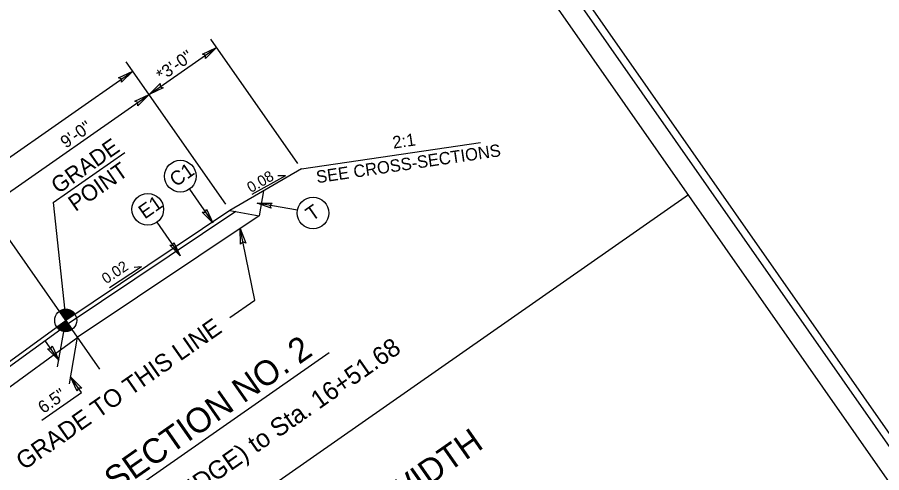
# Model space of a CAD drawing. Extents: x 1033697 to 1037131, y 657437 to 660507.
# Drawn here: x 1036343 to 1036868, y 659641 to 659917 of the extents above; entities that cross this region are included whole.
import ezdxf

# ---------------------------------------------------------------- set-up
doc = ezdxf.new("R2010")
doc.units = 0
for name, color, linetype in [('Default', 7, 'Continuous'), ('Prop Pavement Schedule Description CELL', 7, 'Continuous'), ('Sheet Plot Border Inside CELL', 7, 'Continuous'), ('Sheet Plot Border Outside CELL', 7, 'Continuous'), ('Sheet Typical CELL', 7, 'Continuous'), ('Typical Arrow Superelevation CELL', 7, 'Continuous'), ('Typical Grade Point Symbol CELL', 7, 'Continuous'), ('Typical ID Circle CELL', 7, 'Continuous'), ('Typical Pavement Slope CELL', 7, 'Continuous'), ('Typical Pavement Slope Information CELL', 7, 'Continuous'), ('Typical Shoulder Slope CELL', 7, 'Continuous'), ('Typical Shoulder Slope Information CELL', 7, 'Continuous'), ('Typical Slope Point Local CELL', 7, 'Continuous'), ('Typical Terminator CELL', 7, 'Continuous'), ('Typical Text General CELL', 7, 'Continuous'), ('Typical Text Grade Point CELL', 7, 'Continuous'), ('Typical Text ID Circle CELL', 7, 'Continuous'), ('Typical Text Label CELL', 7, 'Continuous')]:
    doc.layers.add(name, color=color, linetype=linetype)

msp = doc.modelspace()

# ---------------------------------------------------------------- linework, layer by layer
at = {"layer": 'Default'}
for p, q in [((1036513.56, 659828.65), (1036460.77, 659904.21)), ((1036423.33, 659870.49), (1036464.32, 659899.12)), ((1036469.85, 659803.91), (1036409.4, 659890.43)), ((1036216.64, 659747.29), (1036413.38, 659884.73)), ((1036324.96, 659801.76), (1036423.33, 659870.49)), ((1035521.13, 658950.73), (1036750.78, 659809.79)), ((1036393.48, 659703.69), (1036321.41, 659806.85)), ((1036365.07, 659804.89), (1036372.74, 659733.38)), ((1036487.56, 659745.74), (1036478.56, 659789.16)), ((1036472.38, 659735.14), (1036487.56, 659745.74)), ((1036367.74, 659705.17), (1036372.74, 659733.38)), ((1036374.9, 659694.93), (1036379.9, 659723.13)), ((1036368.46, 659709.26), (1036360.5, 659720.65)), ((1036382.24, 659689.54), (1036375.62, 659699.01)), ((1036358.18, 659672.74), (1036382.24, 659689.54))]:
    msp.add_line(p, q, dxfattribs=at)
at = {"layer": 'Sheet Plot Border Inside CELL'}
msp.add_lwpolyline([(1036420.5, 660304.13), (1035054.57, 659349.42), (1035659.01, 658484.62), (1037024.95, 659439.32)], close=True, dxfattribs=at)
at = {"layer": 'Sheet Plot Border Outside CELL'}
msp.add_lwpolyline([(1036411.33, 660325.1), (1035031.05, 659360.38), (1035661.22, 658458.77), (1037041.5, 659423.5)], close=True, dxfattribs=at)
at = {"layer": 'Sheet Typical CELL'}
msp.add_lwpolyline([(1036411.72, 660294.87), (1035182.26, 659435.56), (1035783.78, 658574.94), (1037013.24, 659434.25)], close=True, dxfattribs=at)
at = {"layer": 'Typical Arrow Superelevation CELL'}
for p, q in [((1036506.08, 659821.19), (1036485.7, 659809.88)), ((1036506.08, 659821.19), (1036501.5, 659821.27)), ((1036418.82, 659765.8), (1036399.19, 659753.23)), ((1036418.82, 659765.8), (1036414.25, 659765.59))]:
    msp.add_line(p, q, dxfattribs=at)
at = {"layer": 'Typical Grade Point Symbol CELL'}
for p, q in [((1036372.74, 659733.38), (1036368.89, 659738.88)), ((1036367.24, 659729.53), (1036372.74, 659733.38)), ((1036378.24, 659737.22), (1036372.74, 659733.38)), ((1036376.57, 659727.86), (1036372.74, 659733.38)), ((1036372.74, 659733.38), (1036376.57, 659727.86))]:
    msp.add_line(p, q, dxfattribs=at)
for points in [[(1036368.94, 659738.91), (1036368.94, 659738.91), (1036372.79, 659733.41)], [(1036369.05, 659738.99), (1036372.9, 659733.49)], [(1036369.17, 659739.06), (1036373.01, 659733.56)], [(1036369.28, 659739.13), (1036373.12, 659733.64)], [(1036369.4, 659739.2), (1036373.23, 659733.72)], [(1036369.52, 659739.26), (1036373.34, 659733.79)], [(1036369.64, 659739.33), (1036373.45, 659733.87)], [(1036369.76, 659739.39), (1036373.56, 659733.95)], [(1036369.88, 659739.46), (1036373.67, 659734.03)], [(1036370, 659739.51), (1036373.78, 659734.1)], [(1036370.13, 659739.56), (1036373.89, 659734.18)], [(1036370.26, 659739.61), (1036374, 659734.26)], [(1036370.38, 659739.67), (1036374.11, 659734.33)], [(1036370.52, 659739.71), (1036374.22, 659734.41)], [(1036370.65, 659739.76), (1036374.33, 659734.49)], [(1036370.78, 659739.8), (1036374.44, 659734.56)], [(1036370.92, 659739.84), (1036374.55, 659734.64)], [(1036371.05, 659739.88), (1036374.66, 659734.72)], [(1036371.2, 659739.91), (1036374.77, 659734.79)], [(1036371.34, 659739.94), (1036374.88, 659734.87)], [(1036371.49, 659739.96), (1036374.99, 659734.95)], [(1036371.63, 659739.99), (1036375.1, 659735.03)], [(1036371.78, 659740.02), (1036375.21, 659735.1)], [(1036371.93, 659740.03), (1036375.32, 659735.18)], [(1036372.08, 659740.05), (1036375.43, 659735.26)], [(1036372.23, 659740.07), (1036375.54, 659735.33)], [(1036372.39, 659740.08), (1036375.65, 659735.41)], [(1036372.55, 659740.09), (1036375.76, 659735.49)], [(1036372.71, 659740.09), (1036375.87, 659735.56)], [(1036372.88, 659740.08), (1036375.98, 659735.64)], [(1036373.04, 659740.08), (1036376.09, 659735.72)], [(1036373.21, 659740.08), (1036376.2, 659735.79)], [(1036373.39, 659740.05), (1036376.31, 659735.87)], [(1036373.57, 659740.03), (1036376.42, 659735.95)], [(1036373.75, 659740.01), (1036376.53, 659736.02)], [(1036373.93, 659739.98), (1036376.64, 659736.1)], [(1036374.12, 659739.95), (1036376.75, 659736.18)], [(1036374.31, 659739.9), (1036376.86, 659736.26)], [(1036374.52, 659739.84), (1036376.97, 659736.33)], [(1036374.72, 659739.79), (1036377.08, 659736.41)], [(1036374.94, 659739.72), (1036377.19, 659736.49)], [(1036375.16, 659739.63), (1036377.3, 659736.56)], [(1036375.39, 659739.54), (1036377.41, 659736.64)], [(1036375.62, 659739.43), (1036377.52, 659736.72)], [(1036375.87, 659739.31), (1036377.63, 659736.79)], [(1036376.14, 659739.16), (1036377.74, 659736.87)], [(1036376.43, 659738.98), (1036377.85, 659736.95)], [(1036376.76, 659738.75), (1036377.96, 659737.02)], [(1036377.13, 659738.45), (1036378.07, 659737.1)], [(1036372.1, 659732.93), (1036375.92, 659727.47)], [(1036372.21, 659733.01), (1036376.04, 659727.53)], [(1036372.32, 659733.09), (1036376.16, 659727.59)], [(1036372.43, 659733.16), (1036376.27, 659727.67)], [(1036372.54, 659733.24), (1036376.39, 659727.74)], [(1036372.65, 659733.32), (1036376.5, 659727.81), (1036376.5, 659727.81)], [(1036377.64, 659737.96), (1036378.18, 659737.18)], [(1036367.26, 659729.55), (1036367.68, 659728.95)], [(1036367.37, 659729.63), (1036368.24, 659728.38)], [(1036367.48, 659729.7), (1036368.63, 659728.06)], [(1036367.59, 659729.78), (1036368.97, 659727.81)], [(1036367.7, 659729.86), (1036369.26, 659727.63)], [(1036367.81, 659729.93), (1036369.53, 659727.47)], [(1036367.92, 659730.01), (1036369.78, 659727.34)], [(1036368.03, 659730.09), (1036370.03, 659727.23)], [(1036368.14, 659730.16), (1036370.26, 659727.13)], [(1036368.25, 659730.24), (1036370.48, 659727.05)], [(1036368.36, 659730.32), (1036370.69, 659726.98)], [(1036368.47, 659730.39), (1036370.9, 659726.92)], [(1036368.58, 659730.47), (1036371.1, 659726.86)], [(1036368.69, 659730.55), (1036371.3, 659726.82)], [(1036368.8, 659730.62), (1036371.49, 659726.77)], [(1036368.91, 659730.7), (1036371.68, 659726.74)], [(1036369.02, 659730.78), (1036371.86, 659726.72)], [(1036369.13, 659730.86), (1036372.04, 659726.7)], [(1036369.24, 659730.93), (1036372.21, 659726.68)], [(1036369.35, 659731.01), (1036372.39, 659726.67)], [(1036369.46, 659731.09), (1036372.56, 659726.66)], [(1036369.57, 659731.16), (1036372.72, 659726.66)], [(1036369.68, 659731.24), (1036372.88, 659726.67)], [(1036369.79, 659731.32), (1036373.04, 659726.67)], [(1036369.9, 659731.39), (1036373.2, 659726.67)], [(1036370.01, 659731.47), (1036373.35, 659726.69)], [(1036370.12, 659731.55), (1036373.51, 659726.7)], [(1036370.23, 659731.62), (1036373.66, 659726.72)], [(1036370.34, 659731.7), (1036373.8, 659726.75)], [(1036370.45, 659731.78), (1036373.95, 659726.78)], [(1036370.56, 659731.86), (1036374.09, 659726.8)], [(1036370.67, 659731.93), (1036374.24, 659726.83)], [(1036370.78, 659732.01), (1036374.38, 659726.86)], [(1036370.89, 659732.09), (1036374.52, 659726.9)], [(1036371, 659732.16), (1036374.65, 659726.94)], [(1036371.11, 659732.24), (1036374.79, 659726.98)], [(1036371.22, 659732.32), (1036374.91, 659727.03)], [(1036371.33, 659732.39), (1036375.05, 659727.07)], [(1036371.44, 659732.47), (1036375.18, 659727.13)], [(1036371.55, 659732.55), (1036375.3, 659727.18)], [(1036371.66, 659732.62), (1036375.43, 659727.23)], [(1036371.77, 659732.7), (1036375.56, 659727.28)], [(1036371.88, 659732.78), (1036375.68, 659727.35)], [(1036371.99, 659732.86), (1036375.8, 659727.4)]]:
    msp.add_lwpolyline(points, dxfattribs=at)
msp.add_circle((1036372.73, 659733.37), 6.71, dxfattribs=at)
for start, end in [(34.9294, 124.9294), (214.9294, 304.9294)]:
    msp.add_arc((1036372.73, 659733.37), 6.71, start, end, dxfattribs=at)
at = {"layer": 'Typical ID Circle CELL'}
for p, q in [((1036447.81, 659813.09), (1036462.05, 659792.71)), ((1036513.41, 659800.26), (1036488.93, 659804.6)), ((1036428.06, 659792.95), (1036442.29, 659772.57))]:
    msp.add_line(p, q, dxfattribs=at)
for centre in [(1036442.31, 659820.97), (1036422.55, 659800.83), (1036522.87, 659798.57)]:
    msp.add_circle(centre, 9.62, dxfattribs=at)
at = {"layer": 'Typical Pavement Slope CELL'}
for p, q in [((1036492.87, 659811.99), (1036490.21, 659796.96)), ((1036472.45, 659800.11), (1036372.74, 659733.38)), ((1036476, 659799.48), (1036374.13, 659731.3)), ((1036490.21, 659796.96), (1036379.69, 659722.99)), ((1036472.45, 659800.11), (1036490.21, 659796.96)), ((1036275.78, 659662.71), (1036372.74, 659733.38)), ((1036275.15, 659659.16), (1036374.21, 659731.36)), ((1036272.63, 659644.95), (1036380.1, 659723.27))]:
    msp.add_line(p, q, dxfattribs=at)
at = {"layer": 'Typical Shoulder Slope CELL'}
msp.add_line((1036515.86, 659825.35), (1036472.45, 659800.11), dxfattribs=at)
at = {"layer": 'Typical Slope Point Local CELL'}
msp.add_line((1036515.86, 659825.35), (1036624.59, 659841.36), dxfattribs=at)
at = {"layer": 'Typical Terminator CELL'}
for points in [[(1036455.71, 659895.08), (1036464.32, 659899.12), (1036457.55, 659892.36), (1036457.58, 659894.41)], [(1036404.77, 659880.69), (1036413.38, 659884.73), (1036406.61, 659877.97), (1036406.64, 659880.02)], [(1036431.94, 659874.53), (1036423.33, 659870.49), (1036430.11, 659877.25), (1036430.08, 659875.2)], [(1036414.73, 659866.44), (1036423.33, 659870.49), (1036416.56, 659863.72), (1036416.59, 659865.77)], [(1036497.43, 659801.53), (1036488.93, 659804.6), (1036498.02, 659804.59), (1036496.63, 659803.23)], [(1036458.2, 659800.89), (1036462.05, 659792.71), (1036455.62, 659799.15), (1036457.57, 659799.12)], [(1036478.88, 659779.65), (1036478.56, 659789.16), (1036482.11, 659780.27), (1036480.23, 659781.1)], [(1036438.45, 659780.75), (1036442.29, 659772.57), (1036435.86, 659779.01), (1036437.81, 659778.98)], [(1036364.42, 659717.87), (1036368.46, 659709.26), (1036361.7, 659716.04), (1036363.75, 659716.01)], [(1036379.67, 659690.41), (1036375.62, 659699.01), (1036382.39, 659692.24), (1036380.33, 659692.27)]]:
    msp.add_lwpolyline(points, close=True, dxfattribs=at)
at = {"layer": 'Typical Text Grade Point CELL'}
msp.add_line((1036365.07, 659804.89), (1036408.58, 659835.29), dxfattribs=at)
at = {"layer": 'Typical Text Label CELL'}
msp.add_line((1036329.35, 659571.88), (1036532.58, 659713.86), dxfattribs=at)

# ---------------------------------------------------------------- texts
at = {"layer": 'Default'}
for s, p in [('*3\'-0"', (1036431.06, 659878.3)), ('9\'-0"', (1036372.81, 659837.61)), ('6.5"', (1036359.18, 659676.46))]:
    msp.add_text(s, height=7.5, rotation=34.9389, dxfattribs=at).set_placement(p)
at = {"layer": 'Prop Pavement Schedule Description CELL'}
msp.add_text('SKETCH SHOWING PAVEMENT WIDTH', height=15, rotation=34.9389, dxfattribs=at).set_placement((1036322.14, 659443.2))
at = {"layer": 'Typical Pavement Slope Information CELL'}
msp.add_text('0.02', height=6.476, rotation=33.7932, dxfattribs=at).set_placement((1036397.31, 659755.26))
at = {"layer": 'Typical Shoulder Slope Information CELL'}
msp.add_text('0.08', height=6.476, rotation=30.1775, dxfattribs=at).set_placement((1036485.16, 659810.64))
at = {"layer": 'Typical Slope Point Local CELL'}
for s, p in [('2:1', (1036571.72, 659837.65)), ('SEE CROSS-SECTIONS', (1036525.37, 659816.67))]:
    msp.add_text(s, height=7.5, rotation=8.3739, dxfattribs=at).set_placement(p)
at = {"layer": 'Typical Text General CELL'}
for s, height, p in [('GRADE TO THIS LINE', 10.742, (1036347.34, 659642.03)), ('-L- Sta. 15+64.19 (END BRIDGE) to Sta. 16+51.68 ', 11, (1036304.97, 659524.34))]:
    msp.add_text(s, height=height, rotation=34.9389, dxfattribs=at).set_placement(p)
at = {"layer": 'Typical Text Grade Point CELL'}
for s, p in [('GRADE', (1036368.21, 659809.94)), ('POINT', (1036378.63, 659799.13))]:
    msp.add_text(s, height=9.787, rotation=34.9389, dxfattribs=at).set_placement(p)
at = {"layer": 'Typical Text ID Circle CELL'}
for s, height, p in [('C1', 8.608, (1036439.61, 659814.13)), ('E1', 8.608, (1036420.71, 659794.59)), ('T', 8.61, (1036522.25, 659793.31))]:
    msp.add_text(s, height=height, rotation=34.9389, dxfattribs=at).set_placement(p)
at = {"layer": 'Typical Text Label CELL'}
msp.add_text('TYPICAL SECTION NO. 2', height=15, rotation=34.9389, dxfattribs=at).set_placement((1036329.84, 659577.38))

doc.saveas('drawing.dxf')
